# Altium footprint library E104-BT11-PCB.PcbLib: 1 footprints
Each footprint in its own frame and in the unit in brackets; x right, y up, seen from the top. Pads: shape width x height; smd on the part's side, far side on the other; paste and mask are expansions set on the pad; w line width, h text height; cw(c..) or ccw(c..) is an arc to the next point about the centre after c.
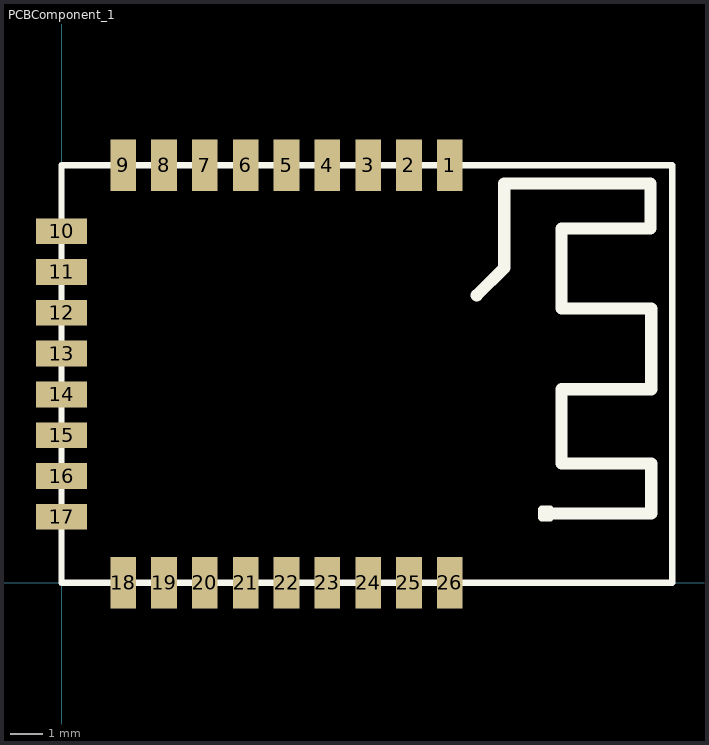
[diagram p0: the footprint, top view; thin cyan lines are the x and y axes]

## PCBComponent_1 [mm]
pads (26):
  rect 0.8x1.6 smd: 1(12.08,13) 2(10.81,13) 3(9.54,13) 4(8.27,13) 5(7,13) 6(5.73,13) 7(4.46,13) 8(3.19,13) 9(1.92,13) 18(1.92,0) 19(3.19,0) 20(4.46,0) 21(5.73,0) 22(7,0) 23(8.27,0) 24(9.54,0) 25(10.81,0) 26(12.08,0)
  rect 1.6x0.8 smd: 10(0,10.945) 11(0,9.675) 12(0,8.405) 13(0,7.135) 14(0,5.865) 15(0,4.595) 16(0,3.325) 17(0,2.055)
Top Overlay:
  lines w0.2: 0,0 0,13 19,13 19,0 0,0
  lines w0.254: 15.2,2.035 14.946,2.035 14.946,2.289 15.2,2.289
  lines w0.381: 12.92,8.95 13.778,9.808 13.778,12.424 18.325,12.424 18.325,11.027 15.556,11.027 15.556,8.538 18.35,8.538 18.35,6.023 15.556,6.023 15.556,3.712 18.35,3.712 18.35,2.162 15.073,2.162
